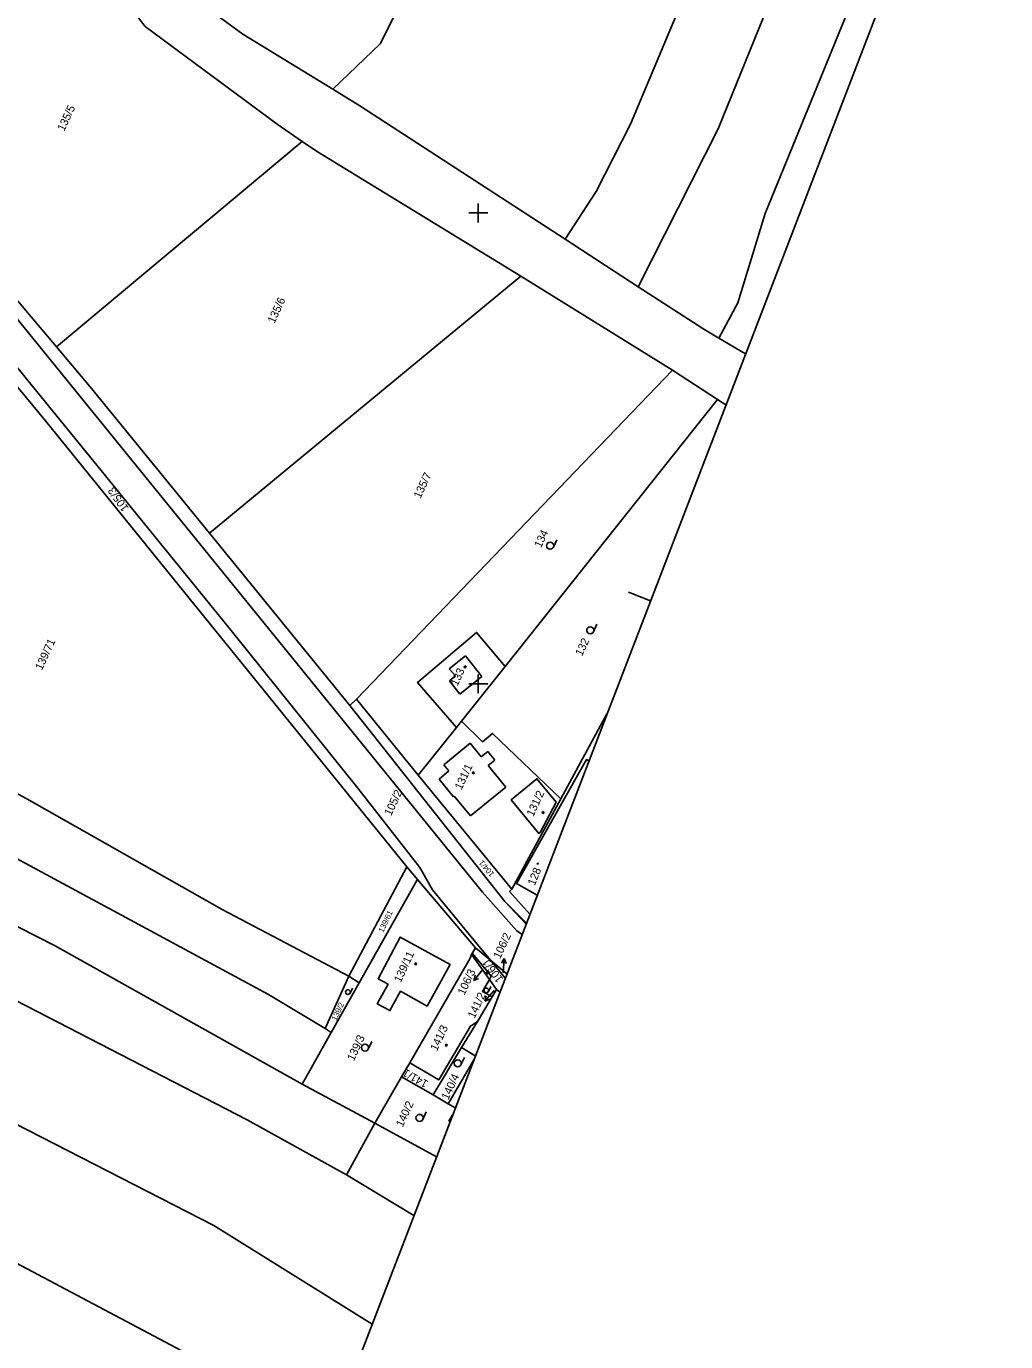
# Model space of a CAD drawing. Extents: x -755344 to -754413, y -1162670 to -1161477.
# Drawn here: x -754696 to -754488, y -1162239.7 to -1161960.4 of the extents above; entities that cross this region are included whole.
import ezdxf

# ---------------------------------------------------------------- set-up
doc = ezdxf.new("R2010")
doc.units = 0
for name, color, linetype in [('Formát', 7, 'Continuous'), ('Síť', 7, 'Continuous'), ('Vrstva 55', 7, 'Continuous'), ('Vrstva 56', 7, 'Continuous'), ('Vrstva 57', 7, 'Continuous'), ('Vrstva 58', 7, 'Continuous'), ('Vrstva 59', 7, 'Continuous')]:
    doc.layers.add(name, color=color, linetype=linetype)

msp = doc.modelspace()

# ---------------------------------------------------------------- linework, layer by layer
at = {"layer": 'Formát'}
msp.add_line((-754563.43, -1162082.36), (-754568.1, -1162080.56), dxfattribs=at)
msp.add_lwpolyline([(-754488.01, -1161886.37), (-754789.71, -1162670.32), (-755344.08, -1162456.97), (-755042.37, -1161673.02)], close=True, dxfattribs=at)
for points in [[(-755344.08, -1162456.97), (-754789.71, -1162670.32), (-754488.01, -1161886.37), (-755042.37, -1161673.02)], [(-755344.08, -1162456.97), (-754789.71, -1162670.32), (-754488.01, -1161886.37), (-755042.37, -1161673.02)], [(-754789.71, -1162670.32), (-754488.01, -1161886.37), (-755042.37, -1161673.02), (-755344.08, -1162456.97)]]:
    msp.add_lwpolyline(points, dxfattribs=at)
at = {"layer": 'Síť'}
for points in [[(-754600, -1161998), (-754600, -1162000), (-754600, -1162002)], [(-754598, -1162000), (-754600, -1162000), (-754602, -1162000)], [(-754600, -1162098), (-754600, -1162100), (-754600, -1162102)], [(-754598, -1162100), (-754600, -1162100), (-754602, -1162100)]]:
    msp.add_lwpolyline(points, dxfattribs=at)
at = {"layer": 'Vrstva 55'}
for p, q in [((-754649.99, -1161962), (-754630.9, -1161973.72)), ((-754649.99, -1161962), (-754630.9, -1161973.72)), ((-754689.56, -1162028.42), (-754731.42, -1161979.09)), ((-754689.56, -1162028.42), (-754637.39, -1161984.8)), ((-754581.59, -1162005.57), (-754566.03, -1162015.68)), ((-754581.59, -1162005.57), (-754566.03, -1162015.68)), ((-754657.11, -1162067.99), (-754590.97, -1162013.45)), ((-754558.74, -1162033.37), (-754590.97, -1162013.45)), ((-754682.41, -1162036.96), (-754689.56, -1162028.42)), ((-754558.74, -1162033.37), (-754625.87, -1162103.25)), ((-754558.74, -1162033.37), (-754549.21, -1162039.61)), ((-754657.11, -1162067.99), (-754682.41, -1162036.96)), ((-754549.21, -1162039.61), (-754594.32, -1162096.35)), ((-754549.21, -1162039.61), (-754547.43, -1162040.77)), ((-754627.26, -1162104.59), (-754657.11, -1162067.99)), ((-754594.32, -1162096.35), (-754603.58, -1162107.92)), ((-754625.87, -1162103.25), (-754627.26, -1162104.59)), ((-754612.76, -1162119.38), (-754625.87, -1162103.25)), ((-754627.26, -1162104.59), (-754594.4, -1162146.25)), ((-754572.68, -1162106.38), (-754582.49, -1162124.43)), ((-754612.76, -1162119.38), (-754604.64, -1162109.25)), ((-754604.64, -1162109.25), (-754603.58, -1162107.92)), ((-754592.91, -1162143.6), (-754612.76, -1162119.38)), ((-754582.49, -1162124.43), (-754592.91, -1162143.6)), ((-754615.21, -1162138.87), (-754627.49, -1162162.07)), ((-754615.21, -1162138.87), (-754612.93, -1162141.56)), ((-754612.93, -1162141.56), (-754600.62, -1162156.1)), ((-754600.62, -1162156.1), (-754601.47, -1162157.47)), ((-754600.62, -1162156.1), (-754597.36, -1162158.77)), ((-754601.47, -1162157.47), (-754601.38, -1162157.59)), ((-754597.66, -1162162.82), (-754601.38, -1162157.59)), ((-754627.49, -1162162.07), (-754632.53, -1162173.22)), ((-754625.29, -1162163.5), (-754627.49, -1162162.07)), ((-754597.66, -1162162.82), (-754596.14, -1162164.94)), ((-754631.23, -1162174.04), (-754625.29, -1162163.5)), ((-754597.06, -1162166.46), (-754596.14, -1162164.94)), ((-754600.21, -1162171.69), (-754597.06, -1162166.46)), ((-754631.23, -1162174.04), (-754637.42, -1162185.04)), ((-754632.53, -1162173.22), (-754631.23, -1162174.04)), ((-754603.57, -1162177.26), (-754600.21, -1162171.69)), ((-754609.61, -1162187.26), (-754603.57, -1162177.26)), ((-754600.64, -1162179.04), (-754603.57, -1162177.26)), ((-754616.28, -1162183.45), (-754614.58, -1162180.53)), ((-754600.96, -1162179.88), (-754606.37, -1162189.2)), ((-754637.42, -1162185.04), (-754622, -1162193.28)), ((-754622, -1162193.28), (-754616.28, -1162183.45)), ((-754609.61, -1162187.26), (-754616.28, -1162183.45)), ((-754606.37, -1162189.2), (-754609.61, -1162187.26)), ((-754606.37, -1162189.2), (-754604.89, -1162190.08)), ((-754622, -1162193.28), (-754608.89, -1162200.48)), ((-754628.02, -1162204.3), (-754613.67, -1162212.89))]:
    msp.add_line(p, q, dxfattribs=at)
for points in [[(-754573.32, -1161853.54), (-754575.25, -1161857.88), (-754609.39, -1161941.34), (-754620.82, -1161964.09), (-754630.9, -1161973.72)], [(-754581.59, -1162005.57), (-754574.99, -1161995.43), (-754567.68, -1161981.15), (-754555.59, -1161952.23), (-754538.63, -1161903.69), (-754525.17, -1161872.07)], [(-754566.03, -1162015.68), (-754549.09, -1161982.12), (-754515.32, -1161898.89), (-754506.22, -1161879.36)], [(-754548.91, -1162026.6), (-754544.92, -1162019.1), (-754539.09, -1162000.11), (-754515.76, -1161942.9), (-754491.63, -1161884.98)], [(-754637.39, -1161984.8), (-754642.71, -1161981.11), (-754670.75, -1161960.4), (-754682.08, -1161945.77), (-754686.04, -1161937.95)], [(-754669.27, -1161943.74), (-754668.12, -1161945.6), (-754662.1, -1161953.11), (-754649.99, -1161962)], [(-754669.27, -1161943.74), (-754668.12, -1161945.6), (-754662.1, -1161953.11), (-754649.99, -1161962)], [(-754630.9, -1161973.72), (-754625.17, -1161977.24), (-754581.59, -1162005.57)], [(-754630.9, -1161973.72), (-754625.17, -1161977.24), (-754581.59, -1162005.57)], [(-754597.36, -1162158.77), (-754599.91, -1162155.71), (-754609.7, -1162143.74), (-754612.4, -1162138.98), (-754625.61, -1162122.15), (-754652.5, -1162088.7), (-754680.12, -1162054.72), (-754695.96, -1162035.25), (-754716.99, -1162009.36), (-754740.8, -1161980.09), (-754741.4, -1161980.31), (-754743.83, -1161981.19)], [(-754742.02, -1161983.57), (-754691.91, -1162044.14), (-754615.21, -1162138.87)], [(-754590.97, -1162013.45), (-754634.36, -1161986.91), (-754637.39, -1161984.8)], [(-754566.03, -1162015.68), (-754552.14, -1162024.71), (-754548.91, -1162026.6)], [(-754566.03, -1162015.68), (-754552.14, -1162024.71), (-754548.91, -1162026.6)], [(-754548.91, -1162026.6), (-754543.25, -1162029.91)], [(-754548.91, -1162026.6), (-754543.25, -1162029.91)], [(-754785.12, -1162078.33), (-754739.17, -1162101.03), (-754695.9, -1162124.41), (-754654.4, -1162147.91), (-754627.49, -1162162.07)], [(-754789.45, -1162089.23), (-754713.23, -1162128.96), (-754644.57, -1162165.98), (-754632.53, -1162173.22)], [(-754594.32, -1162096.35), (-754600.38, -1162089.08), (-754612.9, -1162099.72), (-754604.64, -1162109.25)], [(-754794.8, -1162102.72), (-754733.16, -1162133.64), (-754689.89, -1162155.62), (-754637.42, -1162185.04)], [(-754603.58, -1162107.92), (-754599.13, -1162112.3), (-754596.97, -1162110.52), (-754582.49, -1162124.43)], [(-754799.86, -1162115.47), (-754745.23, -1162143.07), (-754649.07, -1162192.57), (-754628.02, -1162204.3)], [(-754587.49, -1162144.88), (-754591.9, -1162142.38), (-754577.01, -1162116.08), (-754576.52, -1162116.37)], [(-754583.48, -1162125.12), (-754586.89, -1162131.6), (-754587.13, -1162131.76), (-754593.02, -1162124.61), (-754587.57, -1162120.16), (-754583.48, -1162125.12)], [(-754808.43, -1162137.05), (-754656.15, -1162215.06), (-754622.57, -1162236.02)], [(-754612.93, -1162141.56), (-754613.06, -1162141.78), (-754625.29, -1162163.5)], [(-754594.4, -1162146.25), (-754589.78, -1162150.81)], [(-754594.4, -1162146.25), (-754589.87, -1162151.05)], [(-754589.04, -1162148.89), (-754593.36, -1162144.13), (-754592.91, -1162143.6)], [(-754610.85, -1162168.44), (-754616.5, -1162165.29), (-754618.79, -1162169.4), (-754621.47, -1162167.95), (-754619.16, -1162163.81), (-754621.3, -1162162.63), (-754616.57, -1162153.8), (-754605.95, -1162159.62), (-754610.85, -1162168.44)], [(-754601.38, -1162157.59), (-754601.21, -1162157.29), (-754597.24, -1162162.07), (-754597.66, -1162162.82)], [(-754614.58, -1162180.53), (-754601.76, -1162158.25), (-754601.47, -1162157.47)], [(-754593.93, -1162161.59), (-754597.36, -1162158.77)], [(-754594.27, -1162162.48), (-754597.36, -1162158.77)], [(-754817.91, -1162160.94), (-754773.06, -1162183.36), (-754661.89, -1162242.23), (-754631.58, -1162259.43)], [(-754597.66, -1162162.82), (-754598.11, -1162163.63), (-754599.08, -1162165.36), (-754597.06, -1162166.46)], [(-754596.14, -1162164.94), (-754595.44, -1162165.51)], [(-754600.21, -1162171.69), (-754601.66, -1162172.69), (-754608.41, -1162184.14), (-754614.58, -1162180.53)], [(-754606, -1162192.95), (-754606.25, -1162192.8), (-754605.43, -1162191.48)]]:
    msp.add_lwpolyline(points, dxfattribs=at)
at = {"layer": 'Vrstva 56'}
for p, q in [((-754721.12, -1161993.95), (-754599.09, -1162144.22)), ((-754606.16, -1162096.83), (-754602.72, -1162094.03)), ((-754602.72, -1162094.03), (-754599.22, -1162098.47)), ((-754604.83, -1162098.34), (-754606.16, -1162096.83)), ((-754606.14, -1162099.38), (-754604.83, -1162098.34)), ((-754599.22, -1162098.47), (-754603.92, -1162102.18)), ((-754603.92, -1162102.18), (-754606.14, -1162099.38)), ((-754601.76, -1162112.63), (-754607.35, -1162117.18)), ((-754599.41, -1162115.5), (-754601.76, -1162112.63)), ((-754598, -1162114.35), (-754599.41, -1162115.5)), ((-754596.48, -1162116.22), (-754598, -1162114.35)), ((-754607.35, -1162117.18), (-754606.27, -1162118.5)), ((-754597.89, -1162117.37), (-754596.48, -1162116.22)), ((-754594.15, -1162121.96), (-754597.89, -1162117.37)), ((-754606.27, -1162118.5), (-754608.35, -1162120.28)), ((-754608.35, -1162120.28), (-754605.29, -1162124.02)), ((-754605.29, -1162124.02), (-754605.12, -1162123.88)), ((-754605.12, -1162123.88), (-754601.67, -1162128.07)), ((-754601.67, -1162128.07), (-754594.15, -1162121.96)), ((-754599.09, -1162144.22), (-754591.81, -1162152.45)), ((-754591.81, -1162152.45), (-754590.72, -1162153.25)), ((-754601.76, -1162158.25), (-754601.38, -1162157.59)), ((-754622, -1162193.28), (-754628.02, -1162204.3))]:
    msp.add_line(p, q, dxfattribs=at)
at = {"layer": 'Vrstva 57'}
for p, q in [((-754594.54, -1162158.36), (-754595.1, -1162159.33)), ((-754594.73, -1162161.36), (-754594.54, -1162158.36)), ((-754594.54, -1162158.36), (-754594.1, -1162159.4)), ((-754599.03, -1162160.7), (-754600.96, -1162163)), ((-754600.96, -1162163), (-754600.7, -1162161.91)), ((-754600.96, -1162163), (-754599.93, -1162162.55)), ((-754596.67, -1162165.12), (-754598.6, -1162167.42)), ((-754598.6, -1162167.42), (-754598.34, -1162166.33)), ((-754598.6, -1162167.42), (-754597.57, -1162166.98))]:
    msp.add_line(p, q, dxfattribs=at)
at = {"layer": 'Vrstva 58'}
for p, q in [((-754584.07, -1162070.98), (-754583.33, -1162069.4)), ((-754575.56, -1162088.94), (-754574.82, -1162087.36)), ((-754627.23, -1162165.68), (-754626.73, -1162164.61)), ((-754597.86, -1162165.33), (-754597.36, -1162164.26)), ((-754623.38, -1162177.57), (-754622.64, -1162175.99)), ((-754603.69, -1162180.91), (-754602.95, -1162179.33)), ((-754611.81, -1162192.5), (-754611.07, -1162190.92))]:
    msp.add_line(p, q, dxfattribs=at)
for centre, radius in [((-754584.75, -1162070.67), 0.75), ((-754576.24, -1162088.63), 0.75), ((-754627.69, -1162165.46), 0.502), ((-754598.31, -1162165.11), 0.502), ((-754624.06, -1162177.26), 0.75), ((-754604.37, -1162180.6), 0.75), ((-754612.49, -1162192.19), 0.75)]:
    msp.add_circle(centre, radius, dxfattribs=at)
at = {"layer": 'Vrstva 59'}
msp.add_line((-754587.42, -1162138.34), (-754587.31, -1162138.05), dxfattribs=at)
for centre in [(-754602.8, -1162096.4), (-754601.07, -1162118.92), (-754586.24, -1162127.34), (-754613.32, -1162159.48), (-754598.24, -1162161.47), (-754606.78, -1162176.76)]:
    msp.add_circle(centre, 0.175, dxfattribs=at)
msp.add_arc((-754587.29, -1162138.23), 0.175, 99.0834, 218.8179, dxfattribs=at)

# ---------------------------------------------------------------- texts
at = {"layer": 'Vrstva 57'}
for s, height, rotation, p in [('135/5', 1.7, 65, (-754687.95, -1161982.76)), ('135/6', 1.7, 65, (-754643.31, -1162023.59)), ('135/7', 1.7, 65, (-754612.29, -1162060.77)), ('105/3', 1.7, 124.8536, (-754674.15, -1162062.7)), ('134', 1.7, 65, (-754586.69, -1162071.25)), ('132', 1.7, 65, (-754577.98, -1162094.24)), ('139/71', 1.7, 65, (-754692.69, -1162097.23)), ('133', 1.7, 65, (-754604.44, -1162100.6)), ('131/1', 1.7, 65, (-754603.57, -1162122.65)), ('105/2', 1.7, 65, (-754618.52, -1162128.16)), ('131/2', 1.7, 65, (-754588.33, -1162128.33)), ('104/1', 1.2, 130.6051, (-754596.49, -1162140.36)), ('128', 1.7, 67.8956, (-754588.03, -1162142.98)), ('139/61', 1.2, 65, (-754620.2, -1162152.93)), ('106/2', 1.7, 65, (-754595.39, -1162158.54)), ('139/11', 1.7, 65, (-754616.49, -1162163.59)), ('106/1', 1.7, 125.9798, (-754594.63, -1162162.72)), ('106/3', 1.7, 65, (-754602.95, -1162166.24)), ('141/2', 1.7, 65, (-754600.81, -1162171.2)), ('139/2', 1.2, 65, (-754630.15, -1162171.65)), ('141/3', 1.7, 65, (-754608.78, -1162178.13)), ('139/3', 1.7, 65, (-754626.44, -1162180.24)), ('141/1', 1.7, 150.6824, (-754610.51, -1162184.45)), ('140/4', 1.7, 65, (-754606.4, -1162188.48)), ('140/2', 1.7, 65, (-754616.07, -1162194.27))]:
    msp.add_text(s, height=height, rotation=rotation, dxfattribs=at).set_placement(p)

doc.saveas('drawing.dxf')
